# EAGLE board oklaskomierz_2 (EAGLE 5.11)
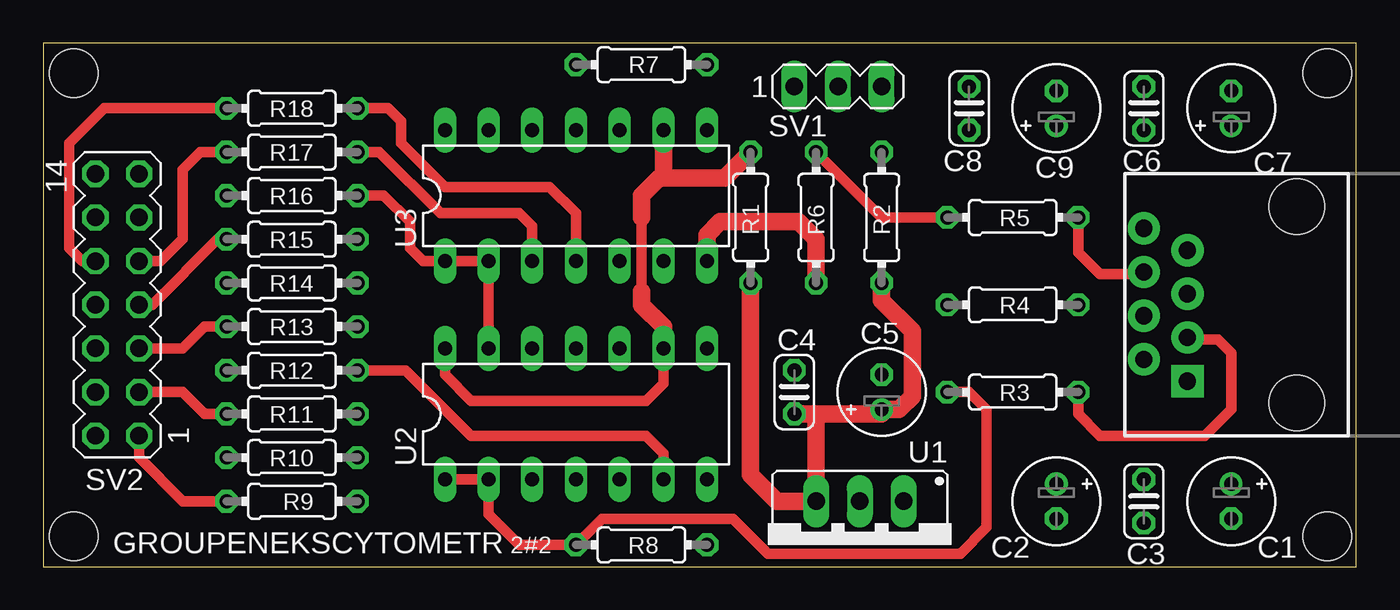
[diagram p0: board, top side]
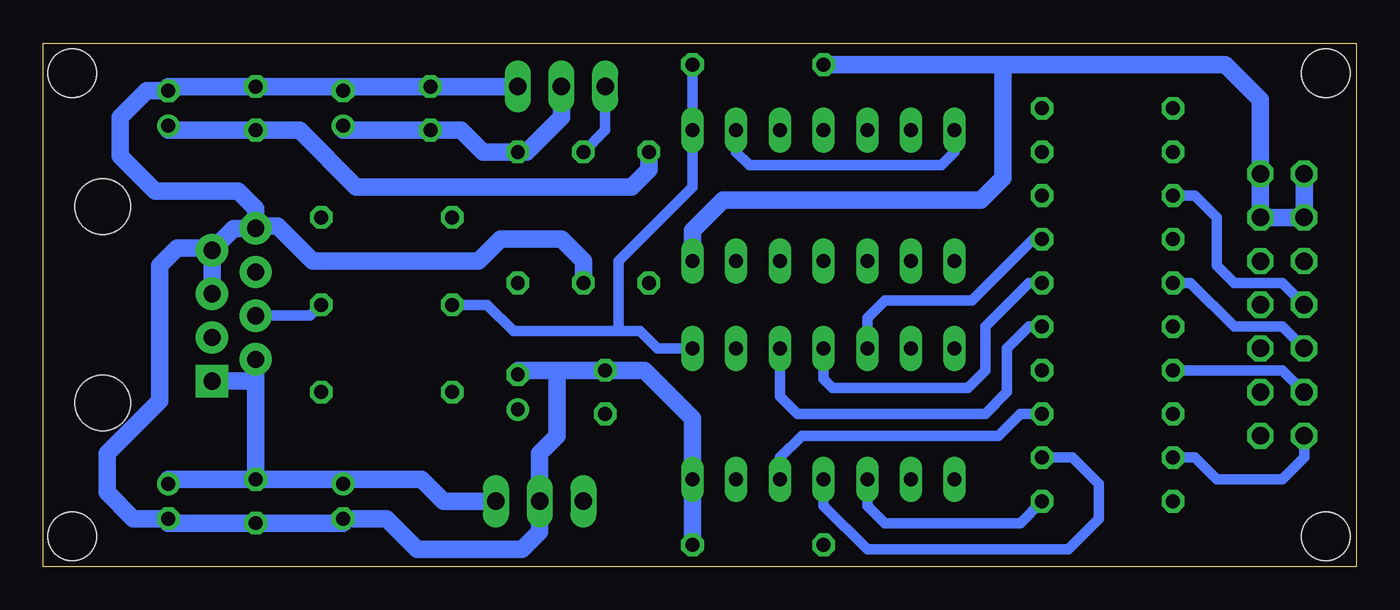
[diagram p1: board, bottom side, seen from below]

Size 76.38 x 30.47 mm. Coordinates in mm from the lower left corner, seen from the top.
Outline: 0,0 76.38,0 76.38,30.47 0,30.47 0,0
Copper layers (1*16): Top 0.035mm / dielectric 1.5mm / Bottom 0.035mm
Design rules "default *": minimum track width 24mil, minimum drill 24mil, track to track 8mil, track to pad 8mil, pad to pad 8mil, via to via 8mil, smd to smd 8mil, copper to edge 40mil, drill to drill 8mil, minimum pad ring 10mil, minimum via ring 8mil, stop-mask expansion 4mil, vias tented up to drill 0mil, thermal gap 10mil
Holes 2.8 mm at 1.78,28.7 1.78,1.78 74.68,1.78 74.68,28.7

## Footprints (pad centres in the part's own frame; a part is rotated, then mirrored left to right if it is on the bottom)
E2-5 = drill 0.813 pad 1.27 round: + -1.016,0 | drill 0.813 pad 1.27 octagon: - 1.016,0
C025-024X044 = drill 0.813 octagon: 1 -1.27,0; 2 1.27,0
0204/7 = drill 0.813 octagon: 1 -3.81,0; 2 3.81,0
MA03-1 = drill 1.016 long: 1 -2.54,0; 2 0,0; 3 2.54,0
MA07-2 = drill 1.016 octagon: 1 -7.62,-1.27; 2 -7.62,1.27; 3 -5.08,-1.27; 4 -5.08,1.27; 5 -2.54,-1.27; 6 -2.54,1.27; 7 0,-1.27; 8 0,1.27; 9 2.54,-1.27; 10 2.54,1.27; 11 5.08,-1.27; 12 5.08,1.27; 13 7.62,-1.27; 14 7.62,1.27
78XXS = drill 1.016 long: GND 0,-2.54; IN -2.54,-2.54; OUT 2.54,-2.54
DIL14 = drill 0.813 long: 1 -7.62,-3.81; 2 -5.08,-3.81; 3 -2.54,-3.81; 4 0,-3.81; 5 2.54,-3.81; 6 5.08,-3.81; 7 7.62,-3.81; 8 7.62,3.81; 9 5.08,3.81; 10 2.54,3.81; 11 0,3.81; 12 -2.54,3.81; 13 -5.08,3.81; 14 -7.62,3.81
RJ45-8 = drill 1 pad 1.88 square: 1 -4.445,6.35 | drill 1 pad 1.88 round: 2 -3.175,8.89; 3 -1.905,6.35; 4 -0.635,8.89; 5 0.635,6.35; 6 1.905,8.89; 7 3.175,6.35; 8 4.445,8.89 | hole 3.2: -5.715,0; 5.715,0

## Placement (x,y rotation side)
C1  470uF  [E2-5]  69.09,3.81 270 top
C2  470uF  [E2-5]  58.93,3.81 270 top
C3  100n  [C025-024X044]  64.01,3.81 270 top
C4  100n  [C025-024X044]  43.69,10.16 90 top
C5  220uF  [E2-5]  48.77,10.16 90 top
C6  100n  [C025-024X044]  64.01,26.67 90 top
C7  100uF  [E2-5]  69.09,26.67 90 top
C8  100n  [C025-024X044]  53.85,26.67 90 top
C9  100uF  [E2-5]  58.93,26.67 90 top
R1  1R  [0204/7]  41.15,20.32 90 top
R2  1R  [0204/7]  48.77,20.32 90 top
R3  10R  [0204/7]  56.39,10.16 180 top
R4  10R  [0204/7]  56.39,15.24 180 top
R5  10R  [0204/7]  56.39,20.32 180 top
R6  680R  [0204/7]  44.96,20.32 90 top
R7  680R  [0204/7]  34.8,29.21 0 top
R8  680R  [0204/7]  34.8,1.27 180 top
R9  [0204/7]  14.48,3.81 180 top
R10  [0204/7]  14.48,6.35 180 top
R11  [0204/7]  14.48,8.89 180 top
R12  [0204/7]  14.48,11.43 180 top
R13  [0204/7]  14.48,13.97 180 top
R14  [0204/7]  14.48,16.51 180 top
R15  [0204/7]  14.48,19.05 180 top
R16  [0204/7]  14.48,21.59 180 top
R17  [0204/7]  14.48,24.13 180 top
R18  [0204/7]  14.48,26.67 180 top
SV1  SERVO  [MA03-1]  46.23,27.94 0 top
SV2  LEDS  [MA07-2]  4.32,15.24 90 top
U1  7805  [78XXS]  47.5,1.27 180 top
U2  74HCT164N  [DIL14]  30.99,8.89 0 top
U3  74HCT164N  [DIL14]  30.99,21.59 0 top
U$1  RJ45-8PTH  [RJ45-8]  72.9,15.24 90 top

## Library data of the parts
C1-C9 R1-R18 = rcl
SV1 SV2 = con-lstb; OC_FARNELL: unknown; OC_NEWARK: unknown
U1 = v-reg
U2 U3 = 74xx-eu
U$1 = SparkFun

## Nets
GND: C1.- C2.- C3.2 C4.2 C5.- C6.2 C7.- C8.2 C9.- R6.1 R7.1 R8.1 SV1.3 SV2.11 SV2.12 SV2.13 SV2.14 U1.GND U2.7 U3.7 U$1.5 U$1.7 U$1.8
LCLK: R4.2 R7.2 U2.8 U3.8
LDTA: R3.2 R8.2 U2.1 U2.2
N$1: C1.+ C2.+ C3.1 U1.IN U$1.1 U$1.2
N$3: R16.1 U2.13 U3.1 U3.2
N$4: R9.1 U2.3
N$5: R10.1 U2.4
N$6: R3.1 U$1.3
N$7: R4.1 U$1.4
N$8: R5.1 U$1.6
N$9: R11.1 U2.5
N$10: R12.1 U2.6
N$11: R13.1 U2.10
N$12: C4.1 C5.+ R1.1 R2.1 U1.OUT
N$13: R14.1 U2.11
N$14: R15.1 U2.12
N$15: R17.1 U3.3
N$16: R18.1 U3.4
N$17: R9.2 SV2.1
N$18: R11.2 SV2.3
N$19: R10.2 SV2.2
N$20: R12.2 SV2.4
N$21: R13.2 SV2.5
N$22: R14.2 SV2.6
N$23: R15.2 SV2.7
N$24: R16.2 SV2.8
N$25: R17.2 SV2.9
N$26: R18.2 SV2.10
SERVO: R5.2 R6.2 SV1.1
VCC: C6.1 C7.+ R1.2 U2.9 U2.14 U3.9 U3.14
VCC2: C8.1 C9.+ R2.2 SV1.2

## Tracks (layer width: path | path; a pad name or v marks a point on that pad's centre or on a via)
GND
  Top 1.016: R6.1 44.96,19.05 43.94,20.07 39.37,20.07 38.61,19.3 U3.7
  Bottom 0.61: U$1.7 66.55,18.54 | C7.- 69.09,27.94 | 58.93,27.94 C9.- | C1.- 69.09,2.54 | 58.93,2.54 C2.- | 48.77,11.43 C5.-
  Bottom 1.016: U$1.5 U$1.7 65.28,19.68 U$1.8 64.01,19.81 | SV1.3 C8.2 58.93,27.94 C6.2 69.09,27.94 | 58.93,2.54 C3.2 69.09,2.54 | SV2.14 SV2.12 SV2.11 SV2.13 5.59,27.18 7.62,29.21 20.57,29.21 | 46.48,11.43 C4.2 41.4,11.43 38.61,8.64 U2.7 R8.1 | 46.48,11.43 48.77,11.43 | 64.01,19.81 62.74,19.81 60.71,17.78 51.05,17.78 49.78,19.05 46.23,19.05 44.96,17.78 R6.1 | C2.- 56.39,2.79 54.61,1.02 48.51,1.02 47.5,2.03 U1.GND 47.5,6.6 46.48,7.62 46.48,11.43 | 66.55,18.54 68.58,18.54 69.6,17.53 69.6,9.65 72.64,6.6 72.64,4.32 71.12,2.79 C1.- | 64.01,19.81 64.01,20.83 65.02,21.84 69.85,21.84 71.88,23.88 71.88,26.16 70.36,27.69 C7.- | U3.7 38.61,19.56 36.83,21.34 21.84,21.34 20.57,22.61 20.57,29.21 | 20.57,29.21 R7.1
LCLK
  Bottom 0.61: 42.93,13.72 49.02,13.72 50.55,15.24 R4.2 | U2.8 40.64,12.7 41.66,13.72 42.93,13.72 | 42.93,13.72 42.93,17.78 38.61,22.1 U3.8 R7.2
LDTA
  Top 0.61: U2.1 U2.2 25.91,3.05 27.69,1.27 R8.2 32.51,2.79 40.13,2.79 42.16,0.76 53.34,0.76 54.86,2.29 54.86,9.14 53.85,10.16 R3.2
N$1
  Bottom 0.61: 69.09,5.08 C1.+ | 58.93,5.08 C2.+ | 64.01,10.67 64.14,10.8
  Bottom 1.016: C3.1 58.93,5.08 54.36,5.08 53.09,3.81 U1.IN | C3.1 69.09,5.08 | C3.1 64.01,10.67 U$1.2 | 64.14,10.8 U$1.1
N$3
  Top 0.61: U2.13 U3.2 U3.1 22.1,17.78 21.34,18.54 21.34,20.07 19.81,21.59 R16.1
N$4
  Bottom 0.61: R9.1 19.56,2.54 25.91,2.54 27.43,2.54 28.45,3.56 U2.3
N$5
  Bottom 0.61: R10.1 16.51,6.35 14.99,4.83 14.99,2.79 16.76,1.02 28.45,1.02 30.99,3.56 U2.4
N$6
  Top 0.61: R3.1 60.2,8.89 61.47,7.62 67.56,7.62 69.09,9.14 69.09,12.45 68.33,13.21 66.67,13.21 U$1.3
N$7
  Bottom 0.61: U$1.4 60.83,14.61 R4.1
N$8
  Top 0.61: R5.1 60.2,18.29 61.47,17.02 64.01,17.02 U$1.6
N$9
  Bottom 0.61: R11.1 19.56,8.89 20.83,7.62 32.26,7.62 33.53,6.35 U2.5
N$10
  Top 0.61: R12.1 21.08,11.43 24.89,7.62 35.05,7.62 36.07,6.6 U2.6
N$11
  Bottom 0.61: R13.1 19.05,13.97 20.32,12.7 20.32,10.16 21.59,8.89 32.51,8.89 33.53,9.91 U2.10
N$12
  Top 0.61: 48.77,8.89 C5.+
  Top 1.016: 44.96,8.89 C4.1 | 44.96,8.89 48.77,8.89 | R2.1 48.77,15.49 50.55,13.72 50.55,9.91 49.78,9.14 C5.+ | 44.96,8.89 U1.OUT 42.67,3.81 41.15,5.33 R1.1
N$13
  Bottom 0.61: R14.1 19.05,16.51 21.59,13.97 21.59,11.43 22.61,10.41 30.48,10.41 30.99,10.92 U2.11
N$14
  Bottom 0.61: R15.1 18.8,19.05 22.35,15.49 27.43,15.49 28.45,14.48 U2.12
N$15
  Top 0.61: R17.1 19.56,24.13 23.11,20.57 27.69,20.57 28.45,19.81 U3.3
N$16
  Top 0.61: R18.1 20.07,26.67 20.83,25.91 20.83,24.64 23.37,22.1 29.46,22.1 30.99,20.57 U3.4
N$17
  Top 0.61: R9.2 8.13,3.81 5.59,6.35 SV2.1
N$18
  Top 0.61: R11.2 9.4,8.89 8.13,10.16 SV2.3
N$19
  Bottom 0.61: R10.2 9.4,6.35 8.13,5.08 4.32,5.08 3.05,6.35 SV2.2
N$20
  Bottom 0.61: R12.2 4.32,11.43 SV2.4
N$21
  Top 0.61: R13.2 9.4,13.97 8.13,12.7 SV2.5
N$22
  Bottom 0.61: R14.2 9.65,16.51 7.11,13.97 4.32,13.97 SV2.6
N$23
  Top 0.61: R15.2 10.16,19.05 6.35,15.24 SV2.7
N$24
  Bottom 0.61: R16.2 9.4,21.59 8.13,20.32 8.13,17.53 7.11,16.51 4.32,16.51 SV2.8
N$25
  Top 0.61: R17.2 9.14,24.13 8.13,23.11 8.13,19.05 6.86,17.78 SV2.9
N$26
  Top 0.61: R18.2 3.56,26.67 1.52,24.64 1.52,18.54 2.29,17.78 SV2.10
SERVO
  Top 0.61: R5.2 48.77,20.32 R6.2
  Bottom 0.61: SV1.1 43.69,25.4 R6.2
VCC
  Top 0.61: 35.81,22.61 36.07,22.61 | 34.8,16 34.8,20.32 | U2.14 23.37,11.18 24.89,9.65 35.05,9.65 36.07,10.67 U2.9
  Top 1.016: 35.81,22.61 34.8,21.59 34.8,20.32 | U3.9 36.07,22.61 39.62,22.61 R1.2 | 34.8,16 34.8,15.24 36.07,13.97 U2.9
  Bottom 0.61: U3.14 23.37,24.13 24.13,23.37 35.31,23.37 36.07,24.13 U3.9 | 69.09,25.4 C7.+
  Bottom 1.016: 69.09,25.4 C6.1 61.47,25.4 58.17,22.1 42.16,22.1 41.15,23.11 R1.2
VCC2
  Bottom 0.61: 58.93,25.4 C9.+
  Bottom 1.016: 58.93,25.4 C8.1 52.07,25.4 50.8,24.13 R2.2 48.26,24.13 46.23,26.16 SV1.2

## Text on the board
tNames: GROUPENEKSCYTOMETR | 2#2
